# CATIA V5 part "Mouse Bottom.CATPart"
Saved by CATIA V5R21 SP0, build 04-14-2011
Part number: Mouse Bottom
Bounding box of the stored display mesh (mm): x -35 to 60, y -31 to 31, z -5 to 1
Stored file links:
  C:\CATIA V5_2015\ASD\Mouse Assembly Template\Mouse Bottom.CATPart
  C:\CATIA V5_2015\ASD\Mouse Assembly Template\Mouse Assembly Template.CATProduct
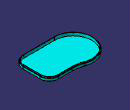
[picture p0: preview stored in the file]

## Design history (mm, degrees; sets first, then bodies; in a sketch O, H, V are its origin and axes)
Set1
  Sketch1 "Mouse Main Sketch", origin (0, 0, 0), H (1, 0, 0), V (0, 1, 0), geometry linked from another document
Set2 "Mouse Bottom Surface"
  Set3 "Cavity Body"
    Set4 "Operation Body"
      Plane1: type Offset, RefPlane xy-plane, Offset -0.5
      Project1 "Parting Curve": ToProject Sketch1, Support Plane1
      Sweep1: type Segment, GuideCrv Project1, Length1 10, Length2 2, Angle 3, DraftDirection xy-plane
      Split1: ToCut xy-plane, Cutting Sketch1
      Offset1: Offset Split1, Length -5
    Fillet1 "Final Cavity Surface": type BiTangent, Element1 Sweep1, Element2 Offset1, Radius 1
  Set5 "Core Body"
    Set6 "Operation Body"
      Sweep2 "Parting Surface": type Segment, GuideCrv Project1, Length1 2, Length2 3, Angle 90, DraftDirection xy-plane
      CurvePar1: Offset Project1, Support Sweep2, Offset2 0, Offset1 -1
      Sweep3: type Segment, GuideCrv CurvePar1, Length1 3, Length2 0, Angle 3, DraftDirection xy-plane
      Offset2: Offset Sweep2, Length -1.5
      Offset3: Offset Sweep1, Length 1.5
      Offset4: Offset Offset1, Length 1.5
      Trim1: Trimmed (Offset4; Offset3)
      Trim2: Trimmed (Sweep2; Sweep3)
      Trim3: Trimmed (Trim2; Offset2)
    Trim4 "Final Core Surface": Trimmed (Trim3; Trim1)
  Trim5 "Mouse Bottom Surface": Trimmed (Trim4; Fillet1)
Body1 (main body)
  Body2
    CloseSurface1: CloseElement Trim5
  Assemble1: tool Body2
